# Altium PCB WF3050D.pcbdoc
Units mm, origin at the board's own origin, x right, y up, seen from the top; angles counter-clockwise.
Board outline 15.74 x 18.23 mm, 2 copper layers (Top Layer, Bottom Layer); 1 components, 0 nets, 4 pads, 0 vias.
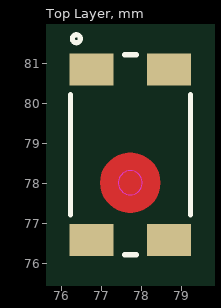
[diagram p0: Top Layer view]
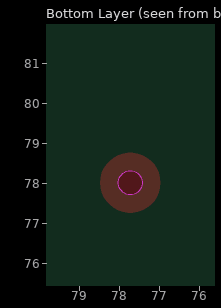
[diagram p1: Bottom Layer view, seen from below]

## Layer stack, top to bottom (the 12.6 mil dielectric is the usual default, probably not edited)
Top Layer: signal copper (thickness not stored)
Dielectric: dielectric 0.32, FR-4, Dk 4.8
Bottom Layer: signal copper (thickness not stored)

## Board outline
85.59,69.85 69.85,69.85 69.85,88.08 85.59,88.08

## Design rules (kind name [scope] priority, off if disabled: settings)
BoardOutlineClearance safeClearance [All] p0: genericclearance=0.254 ignorepadtopadclearanceinfootprint=FALSE except(0: Arc-SplitContinuation Track-SplitContinuation SMDPad-SplitContinuation THPad-SplitContinuation Via-SplitContinuation Fill-SplitContinuation Poly-SplitContinuation Region-SplitContinuation Text-SplitContinuation; 0.152: Track-CutoutEdge SMDPad-CutoutEdge THPad-CutoutEdge Via-CutoutEdge Fill-CutoutEdge Region-CutoutEdge; 0.3: Track-OutlineEdge SMDPad-OutlineEdge THPad-OutlineEdge Via-OutlineEdge Fill-OutlineEdge Region-OutlineEdge Poly-OutlineEdge Text-OutlineEdge)
Clearance safeClearance [All] p1: gap=0.178 ignorepadtopadclearanceinfootprint=FALSE except(0.152: Track-Track Track-SMDPad SMDPad-SMDPad Track-THPad SMDPad-THPad THPad-THPad Track-Via SMDPad-Via THPad-Via Via-Via Track-Fill SMDPad-Fill THPad-Fill Via-Fill Fill-Fill Track-Region SMDPad-Region THPad-Region Via-Region Fill-Region Region-Region Track-Poly SMDPad-Poly THPad-Poly Via-Poly Fill-Poly Region-Poly Poly-Poly Track-Text SMDPad-Text THPad-Text Via-Text Fill-Text Region-Text Poly-Text Text-Text; 0.175: Track-Hole SMDPad-Hole THPad-Hole Via-Hole Fill-Hole Region-Hole Poly-Hole Text-Hole Sheet-Hole; 0.3: Track-Sheet SMDPad-Sheet THPad-Sheet Via-Sheet Fill-Sheet Region-Sheet Poly-Sheet Text-Sheet)
DiffPairsRouting differentialPair [All] p1: maxuncoupledlength=10 minlimit=6 maxlimit=6 mostfreqgap=6 toplayer_minwidth=5 toplayer_prefwidth=10 toplayer_maxwidth=100 bottomlayer_minwidth=5 bottomlayer_prefwidth=10 bottomlayer_maxwidth=100
PasteMaskExpansion pasteMaskExpansion [All] p1: expansion=0
PlaneConnect innerPlane [All] p1: planeconnectstyle=Relief reliefexpansion=0.508 reliefentries=4 reliefconductorwidth=0.254 reliefairgap=0.254
PolygonConnect copperRegion [All] p1: connectstyle=Relief reliefentries=4 reliefconductorwidth=10 polygonreliefangle="90 Angle" airgapwidth=10
RoutingVias viaSize [All] p1: viastyle="Through Hole" holewidth=12.0078 minholewidth=11.811 maxholewidth=236.2204 width=24.0158 minwidth=19.685 maxwidth=393.7008
SolderMaskExpansion solderMaskExpansion [All] p1: useseparateexpansions=TRUE expansion=2 expansionbottom=2
Width trackWidth [All] p1: maxlimit=100 minlimit=5 preferedwidth=10

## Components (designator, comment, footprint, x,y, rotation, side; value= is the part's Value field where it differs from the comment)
? "WF3050" WF3050 77.72,78.73 r0 top

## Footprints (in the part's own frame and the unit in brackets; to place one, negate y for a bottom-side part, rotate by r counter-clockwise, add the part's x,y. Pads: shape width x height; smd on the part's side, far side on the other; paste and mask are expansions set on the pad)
WF3050 [mm]
  rect 1.1x0.8 smd: 1(-0.97,2.13) 2(-0.97,-2.13) 3(0.97,-2.13) 4(0.97,2.13)
  Top Layer region: 0.75,-0.7 0.676,-1.025 0.468,-1.286 0.167,-1.431 -0.167,-1.431 -0.468,-1.286 -0.676,-1.025 -0.75,-0.7 -0.75,-0.7 -0.676,-0.375 -0.468,-0.114 -0.167,0.031 0.167,0.031 0.468,-0.114 0.676,-0.375 0.75,-0.7 hole: 781372.52,780220.611 781365.056,780472.384 781342.69,780723.273 781305.5,780972.396 781253.618,781218.878 781187.224,781461.854 781106.554,781700.47 781011.889,781933.887 780903.563,782161.287 780781.955,782381.87 780647.494,782594.862 780500.651,782799.514 780341.942,782995.108 780171.925,783180.956 779991.197,783356.406 779800.392,783520.841 779600.182,783673.684 779391.268,783814.398 779174.385,783942.488 778950.295,784057.506 778719.785,784159.046 778483.664,784246.752 778242.763,784320.316 777997.926,784379.48 777750.015,784424.036 777499.899,784453.827 777248.458,784468.749 776996.575,784468.749 776745.133,784453.827 776495.018,784424.036 776247.106,784379.48 776002.27,784320.316 775761.368,784246.752 775525.247,784159.046 775294.737,784057.506 775070.647,783942.488 774853.765,783814.398 774644.851,783673.684 774444.64,783520.841 774253.836,783356.406 774073.107,783180.956 773903.09,782995.108 773744.382,782799.514 773597.539,782594.862 773463.077,782381.87 773341.47,782161.287 773233.144,781933.887 773138.479,781700.47 773057.808,781461.854 772991.415,781218.878 772939.532,780972.396 772902.342,780723.273 772879.976,780472.384 772872.512,780220.611 772872.512,780220.611 772879.976,779968.838 772902.342,779717.95 772939.532,779468.827 772991.415,779222.344 773057.808,778979.369 773138.479,778740.753 773233.144,778507.335 773341.47,778279.935 773463.077,778059.352 773597.539,777846.36 773744.382,777641.708 773903.09,777446.114 774073.107,777260.266 774253.836,777084.817 774444.64,776920.381 774644.851,776767.538 774853.765,776626.825 775070.647,776498.734 775294.737,776383.717 775525.247,776282.176 775761.368,776194.47 776002.27,776120.906 776247.106,776061.742 776495.018,776017.186 776745.133,775987.395 776996.575,775972.473 777248.458,775972.473 777499.899,775987.395 777750.015,776017.186 777997.926,776061.742 778242.763,776120.906 778483.664,776194.47 778719.785,776282.176 778950.295,776383.717 779174.385,776498.734 779391.268,776626.825 779600.182,776767.538 779800.392,776920.381 779991.197,777084.817 780171.925,777260.266 780341.942,777446.114 780500.651,777641.708 780647.494,777846.36 780781.955,778059.352 780903.563,778279.935 781011.889,778507.335 781106.554,778740.753 781187.224,778979.369 781253.618,779222.344 781305.5,779468.827 781342.69,779717.95 781365.056,779968.838 781372.52,780220.611
  Board Outline Layer lines w0.025: 0,-1 cw(c0,-0.7) 0,-0.4 cw(c0,-0.7) 0,-1
  Board Outline Layer region: 0,-0.4 -0.13,-0.43 -0.235,-0.513 -0.292,-0.633 -0.292,-0.767 -0.235,-0.887 -0.13,-0.97 0,-1 0,-1 0.13,-0.97 0.235,-0.887 0.292,-0.767 0.292,-0.633 0.235,-0.513 0.13,-0.43 0,-0.4
  Multi-Layer board cut-out: 0,-0.4 -0.13,-0.43 -0.235,-0.513 -0.292,-0.633 -0.292,-0.767 -0.235,-0.887 -0.13,-0.97 0,-1 0,-1 0.13,-0.97 0.235,-0.887 0.292,-0.767 0.292,-0.633 0.235,-0.513 0.13,-0.43 0,-0.4
  silkscreen extent -1.5,-2.5 1.5,3

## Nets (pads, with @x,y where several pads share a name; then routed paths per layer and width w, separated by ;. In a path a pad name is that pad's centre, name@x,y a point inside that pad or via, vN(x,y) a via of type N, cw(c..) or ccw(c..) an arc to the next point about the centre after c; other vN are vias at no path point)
pads on no net: ?.1 ?.2 ?.3 ?.4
